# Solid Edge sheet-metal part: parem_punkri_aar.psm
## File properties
Author: Blackblade
Template: Normal.psm
Last saved by: Blackblade
Revision: 1
Application: Solid Edge
Accuracy: 0.990
Material Thickness: 1.00 mm
Bend Radius: 1.00 mm
Relief Width: 1.00 mm
Relief Length: 0.00 mm
Neutral Factor: 0.330
Minimum Arc Length: 0.10 mm
Deviational Tolerance: 0.10 mm
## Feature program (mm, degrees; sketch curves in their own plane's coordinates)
base tab "unnamed BaseTab 1"
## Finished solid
Body 1: solid body, 4 faces, 6 edges, 4 vertices.
  Faces by surface: plane 3, cylinder 1
  Edges by curve: line 4, circle 2
Bounding box of the edges (mm): 170.000 x 14.464 x 1.000, from (-68.3271, -72.2809, 0) to (101.6729, -57.8171, 1).
Cylindrical faces by radius (mm): R649 x1
Planar faces by outward normal: +z 1, -z 1, oblique 1
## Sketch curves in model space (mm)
arc centre (67.9255, 576.7191, 0) radius 649 from (-68.3271, -57.8171, 0) through (16.2247, -70.2183, 0) to (101.6729, -71.4029, 0)
line (-68.3271, -57.8171, 0) -> (101.6729, -71.4029, 0)
arc centre (67.9255, -577.5355, 0) radius 649 from (-68.3271, 57.0007, 0) through (16.2247, 69.4019, 0) to (101.6729, 70.5865, 0)
line (101.6729, 70.5865, 0) -> (-68.3271, 57.0007, 0)
arc centre (67.9255, 576.7191, 0) radius 649 from (-116.258, -45.5971, 0) through (128.625, -69.4361, 0) to (364.7842, -0.4082, 0)
arc centre (-50.426, -0.4082, 0) radius 79.8492 from (-130.2752, -0.4082, 0) through (-126.6904, -24.0647, 0) to (-116.258, -45.5971, 0)
arc centre (-50.426, -0.4082, 0) radius 79.8492 from (-130.2752, -0.4082, 0) through (-126.6904, 23.2483, 0) to (-116.258, 44.7807, 0)
arc centre (67.9255, -577.5355, 0) radius 649 from (-116.258, 44.7807, 0) through (128.625, 68.6197, 0) to (364.7842, -0.4082, 0)
arc centre (67.9255, -577.5355, 0) radius 649 from (-68.3271, 57.0007, 0) through (-92.6009, 51.2986, 0) to (-116.6378, 44.6682, 0)
arc centre (-50.426, -0.4082, 0) radius 80.0992 from (-116.6378, -45.4846, 0) through (-130.5252, -0.4082, 0) to (-116.6378, 44.6682, 0)
arc centre (67.9255, 576.7191, 0) radius 649 from (-116.6378, -45.4846, 0) through (-92.6009, -52.115, 0) to (-68.3271, -57.8171, 0)
line (-68.3271, -57.8171, 0) -> (-68.3271, 57.0007, 0)
line (101.6729, -71.4029, 0) -> (101.6729, 70.5865, 0)
arc centre (67.9255, 576.7191, 0) radius 649 from (101.6729, -71.4029, 0) through (236.9969, -49.8715, 0) to (364.7842, -0.4082, 0)
arc centre (67.9255, -577.5355, 0) radius 649 from (364.7842, -0.4082, 0) through (236.9969, 49.0552, 0) to (101.6729, 70.5865, 0)
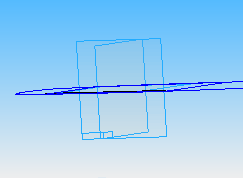
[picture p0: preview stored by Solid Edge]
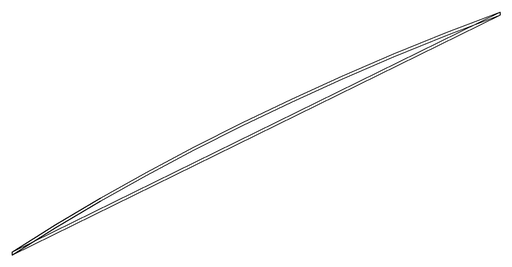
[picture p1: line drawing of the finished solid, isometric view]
